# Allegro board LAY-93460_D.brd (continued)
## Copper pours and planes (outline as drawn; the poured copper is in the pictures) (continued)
MCU_LINK_3V3 on TOP: 41.67,19.5 43.43,19.5 43.58,19.35 45.35,19.35 45.58,19.58 45.58,20.01 45.33,20.27 43.86,20.27 43.17,20.95 41.67,20.95
MLINK_3V3 on BOTTOM: 62.08,2.97 62.74,2.97 63.02,2.7 63.97,2.7 64.18,2.49 64.18,1.98 63.8,1.6 62.51,1.6 62.34,1.75 62.08,1.75
RF_A on TOP (solid shape): 76.17,27.73 76.31,27.71 76.45,27.67 77.66,27.07 77.47,26.69 76.52,27.16 76.42,27.26 76.35,27.36 76.2,27.51 76,27.57 75.84,27.57 75.84,27.73
RF_ANT_1 on TOP: 96.6,15.17 89.73,20.5 89.5,20.27 94.83,13.4
RF_ANT_2 on TOP: 96.6,40.83 89.73,35.5 89.5,35.73 94.83,42.6
RF_B on TOP (solid shape): 77.66,28.93 76.45,28.33 76.31,28.29 76.17,28.27 75.84,28.27 75.84,28.43 76,28.43 76.2,28.49 76.35,28.63 76.42,28.74 76.52,28.84 77.47,29.31
SW_50 on TOP: 73.64,28.47 73.64,27.53 73.92,27.53 74.18,27.79 74.73,27.79 74.85,27.92 75.22,27.92 75.22,28.08 74.85,28.08 74.74,28.21 74.18,28.21 73.92,28.47
V_LDO_OUT on TOP: 33.6,52.46 33.82,52.24 35.43,52.24 35.63,52.03 35.63,51.36 35.95,51.04 37.65,51.04 38.34,51.74 39.66,51.74 39.76,51.84 39.76,53.22 39.62,53.37 38.29,53.37 37.62,54.03 34.19,54.03 33.6,53.44

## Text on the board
BOTTOM: 170-93460 REV D | 09 | L6_SS
Board Geometry/Soldermask Bottom: 10 | SECONDARY SOLDERMASK
Ref Des/Silkscreen Bottom: D | IN TO OUT2 | INS LOSS | ISOLATION | IN TO OUT1 | VCTL (PIN 4) | 0 | 1 | VDD (PIN 6) | SN | SCH | 700 | 11 | SECONDARY SILKSCREEN
User.Comments: 1 OF 1 | TEST PROBE | 1/1 | 1 | 2
TOP: 04 | L1_PS
Board Geometry/Soldermask Top: 03 | PRIMARY SOLDERMASK
Ref Des/Silkscreen Top: INT | A | C | PWM | ADC | RST | CS | RX | SCK | TX | SCL | MISO | SDA | MOSI | 5V0 | 3V3 | GND | B | 1-2 | DCDC MODE | 2-3 | BYPASS MODE | JP10 VDD_BRD | KW47-LOC | 02 | PRIMARY SILKSCREEN
L2_GND_1: 05 | L2_GND_1
L3_INT_1: 06 | L3_INT_1
L4_INT_2: 07 | L4_INT_2
L5_GND_2: 08 | L5_GND_2
XSECTION_CHART: L4_INT_2 | L3_INT_1 | LAYERS | L1_PS | L6_SS | TRACE WIDTH | N/A | SE | IMPEDANCE | 8.96 | TRACE SPACING | 5.04 | 90.00 | REFERENCE LAYER | 5 | 2 | DIFF | 5.62 | 7.80 | 6.20 | 8.38 | 100.00 | 16.43 | COPLANAR | 15.41 | GAP | 50.00 | BOARD THICKNESS TOLERANCE +/-10% | ALL VALUES ARE FINISHED VALUES | SCALE: NONE | 16 | 22 | 23. INTENTIONAL 29 SHORTS AT: | LocationStart     LocationEnd       RefDes       Net 1            Net 2 | (210.00 303.00) (210.00 343.00)     SH1       RESET           RST_TGTMCU_B | (110.00 303.00) (110.00 343.00)     SH2       AN              ADC_IN | (131.26 936.26) (131.26 1015.00)    JS5       UART0_RX        UART_RX | (210.00 1015.00) (210.00 936.26)    JS6       UART0_TX        UART_TX | (66.00 980.00) (66.00 1020.00)      SH3       PTD2/TMP1_CH0   PWM | (97.24 1301.26) (97.24 1380.00)     JS4       P5V_CAN         FL_USB_5V0 | (310.00 303.00) (310.00 343.00)     SH4       SPI_PSC0        LPSPI_PCS0 | (410.00 303.00) (410.00 343.00)     SH6       SPI_SCK         LPSPI_SCK | (470.00 1060.00) (510.00 1060.00)   SH11      I2C1_SCL        I2C_SCL | (295.00 1060.00) (335.00 1060.00)   SH5       WUU0_P12/NMI_B  LLWU/NMI_B | (682.80 31.26) (682.80 110.00)      JS2       P_LED           V_BRD | (610.00 303.00) (610.00 343.00)     SH10      SPI_SOUT        LPSPI_SOUT | (510.00 303.00) (510.00 343.00)     SH8       SPI_SIN         LPSPI_SIN | (570.00 1060.00) (610.00 1060.00)   SH13      PTD3/I2C1_SDA   I2C_SDA | (710.00 300.00) (710.00 340.00)     SH12      3V3_MIKROE      V_BRD | (750.00 1060.00) (710.00 1060.00)   SH14      P5V             5V_MIKROE | (1095.71 -2.04) (1095.71 -80.78)    JS14      TMP1_CH0        LED1_B1 | (1498.86 1619.02) (1498.86 1682.02) SH19      P3V3_LDO        V_BRD | (1802.41 505.60) (1762.41 505.60)   SH15      V_BRD           VCC_TGMCU | (1782.74 1781.74) (1782.74 1741.74) SH21      VDD_IC          P_VDD_SWITCH | (1849.10 -7.06) (1849.10 55.94)     SH20      BOOT_CFG        SWO/BOOT_CFG | (2094.30 1414.97) (1994.30 1414.97) JS11      UART1_TX        N23938761 | (2094.30 1289.97) (1994.30 1289.97) JS10      UART1_RX        N23938720 | (2094.30 1539.97) (2015.56 1539.97) JS1       VDD_MEM         V_BRD | (2454.01 318.43) (2454.01 358.43)   SH22      N24374306       VDD_DCDC | (2445.41 1289.97) (2485.41 1289.97) SH23      N24374396       VDD_RF | (2620.82 80.95) (2620.82 159.69)    JS3       RST_TGTMCU_B    LED_RTS | (2672.48 922.47) (2732.48 922.47)   SH24      RF_GPO_5        N24516334 | (2722.41 424.47) (2722.41 484.47)   SH9       RF_GPO_4        N24441947 | *  SURFACE - AIR 0 MIL | *  DIELECTRIC - DRY_FILM_MASK 0.3 MIL | L1 TOP CONDUCTOR - COPPER 1.83 MIL | *  DIELECTRIC - IT-180ABS 10.16 MIL | L2 L2_GND_1 PLANE - COPPER 1.18 MIL | *  DIELECTRIC - IT-180ABS 10 MIL | L3 L3_INT_1 CONDUCTOR - COPPER 1.18 MIL | *  DIELECTRIC - IT-180ABS 9.6 MIL | L4 L4_INT_2 CONDUCTOR - COPPER 1.18 MIL | L5 L5_GND_2 PLANE - COPPER 1.18 MIL | L6 BOTTOM CONDUCTOR - COPPER 1.83 MIL | DESIGN CROSS SECTION CHART | ___________________________ | TOTAL THICKNESS 58.9 MIL | 1-6 | 19 | *IMPEDANCE TABLE VALUES ARE BASED ON THE FAB VENDOR SUPPLIED STACK-UP | IF ANY IMPEDANCE IS NOT FOUND ON A SPECIFIC LAYER, PLEASE IGNORE IT | DETAIL | IMPEDANCE REQUIREMENTS | IMPEDANCE TOLERANCE IS 10% | LAYER STACKUP | B | A
DIMENSION: (X2) | PRIMARY DATUM | GRID ORIGIN
BODY_CENTER: 01 | PRIMARY PASTEMASK
COMPVAL_TYPE_BOTTOM: 12 | SECONDARY PASTEMASK
User.8: OF 12
User.10: 22. THIS FAB_VIAFILL.ART SHOWS LOCATIONS OF VIA-IN-PAD TO BE FILLED. | 1/1 | 2
User.11: 1/1 | 3
User.12: 09-18-25 | 07-10-25 | 02-24-25 | 06-02-25 | A.Q. | J.R. | E.L. | M.E. | B | B1 | C | D | C165 AND R32 ADDED | WIDTH AND GAP UPDATED FOR RF TRACE | XTAL ROUTING IMPROVED | SECOND RELEASE | THIRD RELEASE-PCB SUPPLIER UPDATE | PRODUCTION RELEASE
User.17: FIGURE | SIZE | 8.0 | 8.1 | 16.0 | 28.0 | 35.0 | 40.0 | 63.0 | 100.0 | 118.0 | 55.0x24.0 | 83.0x24.0 | 111.0x32.0 | 122.0x32.0 | DRILL CHART: TOP to BOTTOM | ALL UNITS ARE IN MILS | TOLERANCE | +0.0/-8.0 | +0.0/-8.1 | +2.0/-2.0 | +3.0/-3.0 | PLATED | NON-PLATED | QTY | 1488 | 193 | 16 | 20 | 5 | 57 | 8 | 30 | 1 | 2 | 3
